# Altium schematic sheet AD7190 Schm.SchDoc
size A3
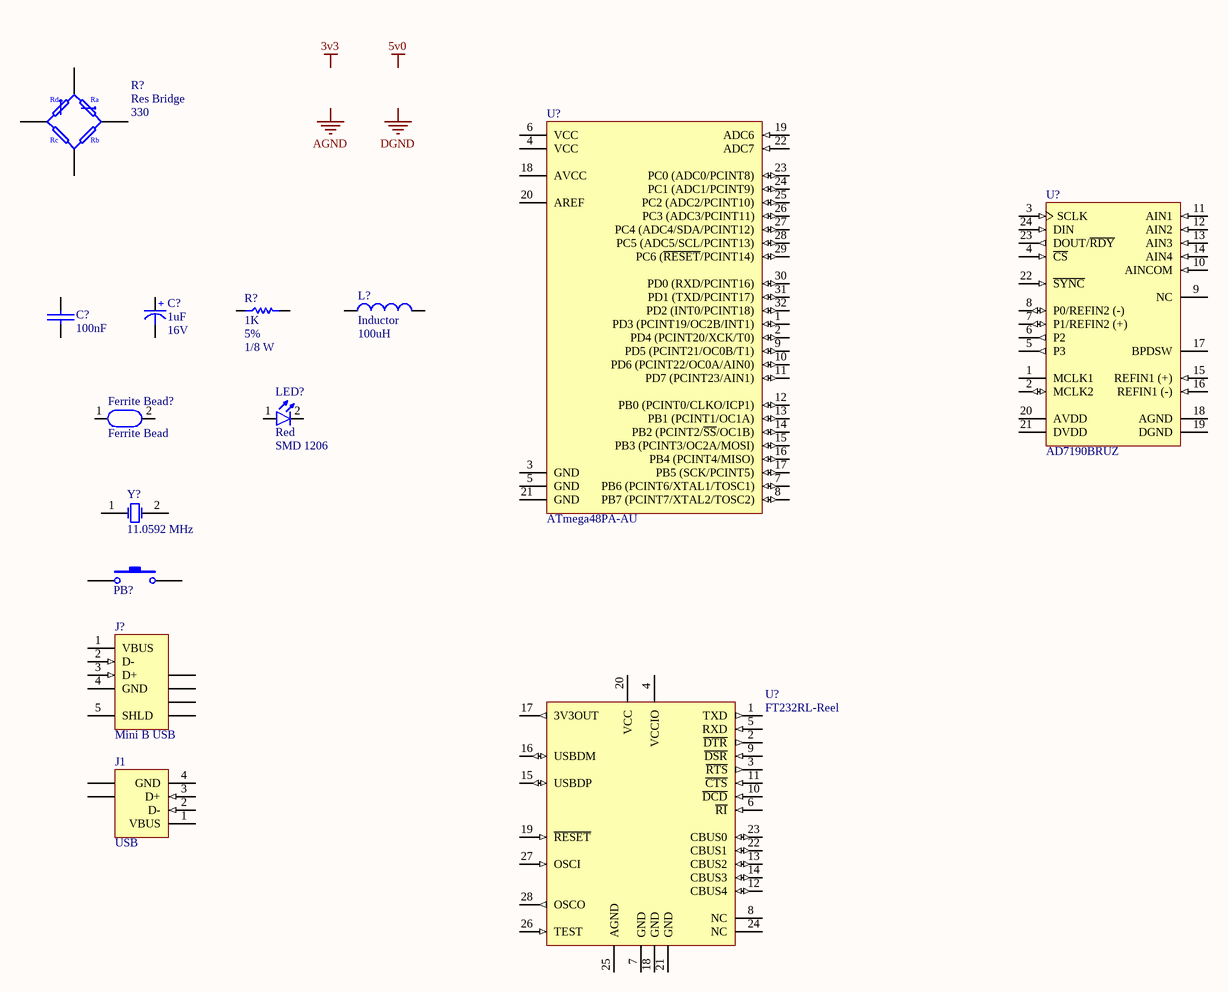
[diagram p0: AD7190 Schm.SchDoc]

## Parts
(Parts that share a designator on the sheet are numbered #1, #2 ... from top to bottom, then left to right.)
C?#1  100nF  [SMD_CAP_1206]
C?#2  Voltage: 16V  [cap 01]  (hidden comment: 1uF)
Ferrite_Bead?  Ferrite Bead  [1206]
J1  USB  [1-1470156]
J?  Mini B USB  [Mini B USB]
L?  Inductor  value 100uH  [INDC101SMD]
LED?  Size: SMD 1206  [LED SMD 1206]  (hidden comment: Red)
PB?  Push Button  [Push Button]  (value not drawn)
R?#1  Res Bridge  value 330  [P04A]
R?#2  Tolerance: 5%  Power: 1/8 W  [RES 0805 (2012X06L)]  (hidden comment: 1K)
U?#1  ATmega48PA-AU  [32A_N]
U?#2  AD7190BRUZ  [RU-24_N]
U?#3  FT232RL-Reel  [SSOP-28_N]
Y?  11.0592 MHz  [XTAL Small]

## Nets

Not connected (* = marked no-connect by the designer): C?#1 1(+) 2(-); C?#2 1(+) 2(-); Ferrite_Bead? 1 2; J1 1(VBUS) 2(D-) 3(D+) 4(GND) 5(SHLD) 6(SHLD); J? 1(VBUS) 2(D-) 3(D+) 4(GND) 5(SHLD) 6(SHLD) 7(SHLD) 8(SHLD) 9(SHLD); L? 1 2; LED? 1(A) 2(K); PB? 1 2; R?#1 1 2 3 4; R?#2 1 2; U?#1 1(PD3_(PCINT19/OC2B/INT1)) 2(PD4_(PCINT20/XCK/T0)) 3(GND) 4(VCC) 5(GND) 6(VCC) 7(PB6_(PCINT6/XTAL1/TOSC1)) 8(PB7_(PCINT7/XTAL2/TOSC2)) 9(PD5_(PCINT21/OC0B/T1)) 10(PD6_(PCINT22/OC0A/AIN0)) 11(PD7_(PCINT23/AIN1)) 12(PB0_(PCINT0/CLKO/ICP1)) 13(PB1_(PCINT1/OC1A)) 14(PB2_(PCINT2/~{SS}/OC1B)) 15(PB3_(PCINT3/OC2A/MOSI)) 16(PB4_(PCINT4/MISO)) 17(PB5_(SCK/PCINT5)) 18(AVCC) 19(ADC6) 20(AREF) 21(GND) 22(ADC7) 23(PC0_(ADC0/PCINT8)) 24(PC1_(ADC1/PCINT9)) 25(PC2_(ADC2/PCINT10)) 26(PC3_(ADC3/PCINT11)) 27(PC4_(ADC4/SDA/PCINT12)) 28(PC5_(ADC5/SCL/PCINT13)) 29(PC6_(~{RESET}/PCINT14)) 30(PD0_(RXD/PCINT16)) 31(PD1_(TXD/PCINT17)) 32(PD2_(INT0/PCINT18)); U?#2 1(MCLK1) 2(MCLK2) 3(SCLK) 4(~{CS}) 5(P3) 6(P2) 7(P1/REFIN2_(+)) 8(P0/REFIN2_(-)) 9(NC) 10(AINCOM) 11(AIN1) 12(AIN2) 13(AIN3) 14(AIN4) 15(REFIN1_(+)) 16(REFIN1_(-)) 17(BPDSW) 18(AGND) 19(DGND) 20(AVDD) 21(DVDD) 22(~{SYNC}) 23(DOUT/~{RDY}) 24(DIN); U?#3 1(TXD) 2(~{DTR}) 3(~{RTS}) 4(VCCIO) 5(RXD) 6(~{RI}) 7(GND) 8(NC) 9(~{DSR}) 10(~{DCD}) 11(~{CTS}) 12(CBUS4) 13(CBUS2) 14(CBUS3) 15(USBDP) 16(USBDM) 17(3V3OUT) 18(GND) 19(~{RESET}) 20(VCC) 21(GND) 22(CBUS1) 23(CBUS0) 24(NC) 25(AGND) 26(TEST) 27(OSCI) 28(OSCO); Y? 1(OSC1) 2(OSC2)

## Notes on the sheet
- Labels drawn without touching a wire or pin: 3v3, 5v0, AGND, DGND

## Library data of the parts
C?#1 = Cap-Bipolar: Bipolar Capacitor; Voltage: 100V; Designer: Saeid Jorablo; Organazation: ControTec
C?#2 = Cap-Polar: Polar Capacitor; Designer: Saeid Jorablo; Organazation: ControTec
J1 = 1-1470156-2: USB 1.1, Right Angle, Thru-Hole, B Type, Receptacle, 4 Position, Black; ContactMaterial: Phosphor Bronze; ContactPlating: Gold over Nickel; TerminationLength: 3.00mm [0.118in.]; PCB_Layout: Complies with manufacturer's recommendation.; DrillSize: Corresponds to nominal value.; PanelGround: Without
J? = Mini B USB: USB 2.0, Right Angle, SMT, A Type, Receptacle, 5 Position, Black; ContactMaterial: Phosphor Bronze; ContactPlating: Gold (30) over Nickel; PCB_Layout: Complies with manufacturer's recommendation.; DrillSize: Corresponds to nominal value.; PanelGround: Without
L? = Inductor: Code_IEC: 1005
LED? = LED: Designer: Saeid Jorablo; Organazation: ControTec
R?#1 = Res Bridge: Resistor Bridge
R?#2 = Resistor
U?#1 = ATmega48PA-AU: 8-bit AVR Microcontroller, 4KB Flash, 256 Bytes EEPROM, 512 Bytes SRAM, 32-pin TQFP, Industrial Grade (-40°C to 85°C)
U?#2 = AD7190BRUZ: Quad 24-Bit Ultralow Noise Sigma-Delta Analog-to-Digital Converter with Serial, SPI Interface and PGA, 4.8KSPS, -40 to +105 degC, RU-24, Pb-Free, Tube; Generic Part Number: AD7190; Manufacturer: Analog Devices; Resolution (Bits): 24; Channels: 4; Throughput Rate (SPS): 4.8K; Interface: Ser, SPI
U?#3 = FT232RL-Reel: USB UART Asynchronous Serial Data Transfer Chip, 28-pin SSOP, Tape and Reel; Manufacturer: FTDI
Y? = XTAL: XTAL Crystal; Company: E.P.I.L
